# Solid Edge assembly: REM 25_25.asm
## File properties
Title: Zylinder
Author: ahadarics
Template: iso metric assembly.asm
Last saved by: ahadarics
Revision: 3
Application: Solid Edge
Username: ahadarics
Dokumentum tartalom típus: 1
Document Number: REM 25/25
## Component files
Profilrohr.par
Kolbenstange.par
Kit_1.par
Kit_2.par
Mutter_1.par
Mutter_2.par
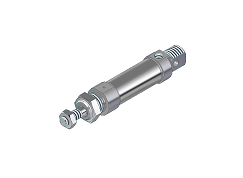
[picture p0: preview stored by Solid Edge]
